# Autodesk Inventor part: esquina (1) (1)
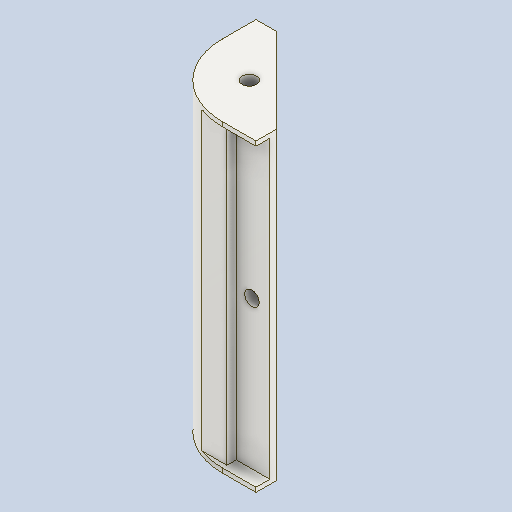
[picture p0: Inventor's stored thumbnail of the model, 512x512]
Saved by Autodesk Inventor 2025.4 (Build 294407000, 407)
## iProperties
Created: 2026-06
Part Number: esquina (1) (1)
Material: Generic
Document SubType Name: Modeling
Designer: AdminForWorker
Density: 1 g/cm^3
Appearance: Default
Title: esquina (1) (1)
Author: AdminForWorker
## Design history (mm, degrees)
feature "esquina (1) (1)"
body "Solid1"
